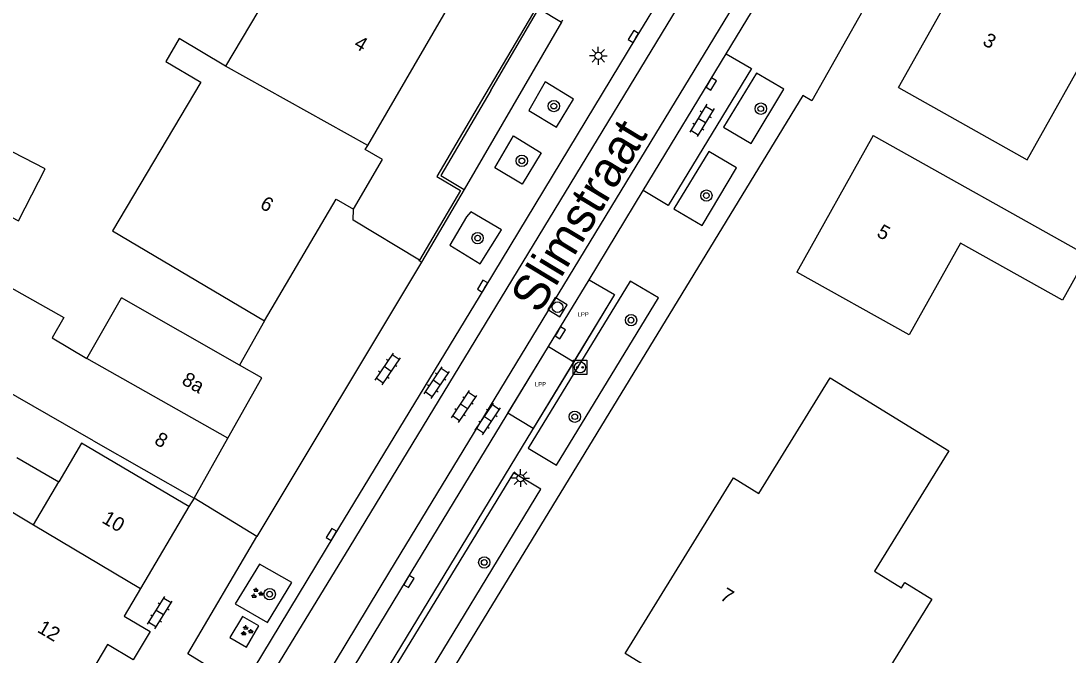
# Model space of a CAD drawing. Extents: x 136000 to 141014, y 402000 to 403500.
# Drawn here: x 137884.6 to 137958.3, y 402514.4 to 402559.1 of the extents above; entities that cross this region are included whole.
import ezdxf

# ---------------------------------------------------------------- set-up
doc = ezdxf.new("R2010")
doc.units = 0
for name, color, linetype in [('bp-grn-parkeervak', 7, 'Continuous'), ('gg-afsc-erfafscheiding', 7, 'Continuous'), ('gg-afsc-muur', 7, 'Continuous'), ('gg-anno-huisnummerreeks BGT', 7, 'Continuous'), ('gg-anno-openbare ruimte label', 7, 'Continuous'), ('gg-bbg-gedigitaliseerde bebouwing', 7, 'Continuous'), ('gg-bbg-gedigitaliseerde bijgebouw', 7, 'Continuous'), ('gg-bbg-hoofdgebouw', 7, 'Continuous'), ('gg-bbg-tussenscheiding', 7, 'Continuous'), ('gg-knt-verharding', 7, 'Continuous'), ('gg-knt-verharding nz', 7, 'Continuous'), ('gt-symb-boom', 7, 'Continuous'), ('gt-symb-groenvak', 7, 'Continuous'), ('gt-symb-klinker verharding', 7, 'Continuous'), ('gt-symb-kolk', 7, 'Continuous'), ('gt-symb-laadpunt elektrisch vervoer', 7, 'Continuous'), ('gt-symb-lichtmast', 7, 'Continuous'), ('gt-symb-rioolschacht', 7, 'Continuous'), ('kenmerkpunt laadpunt parkeerplaats', 7, 'Continuous')]:
    doc.layers.add(name, color=color, linetype=linetype)

# ---------------------------------------------------------------- blocks, each defined once
blk = doc.blocks.new('gt0-BOOM')
at = {"layer": 'gt-symb-boom'}
for radius in [0.4, 0.2]:
    blk.add_circle((0, 0), radius, dxfattribs=at)
blk = doc.blocks.new('gt0-LMAST')
at = {"layer": 'gt-symb-lichtmast'}
for p, q in [((-0.182, 0.173), (-0.447, 0.438)), ((-0.005, 0.246), (-0.005, 0.621)), ((0.172, 0.173), (0.437, 0.438)), ((-0.255, -0.004), (-0.63, -0.004)), ((-0.182, -0.181), (-0.447, -0.446)), ((-0.005, -0.254), (-0.005, -0.629)), ((0.437, -0.446), (0.172, -0.181)), ((0.245, -0.004), (0.62, -0.004))]:
    blk.add_line(p, q, dxfattribs=at)
blk.add_circle((-0.005, -0.004), 0.25, dxfattribs=at)
blk = doc.blocks.new('gt0-KOLK')
at = {"layer": 'gt-symb-kolk'}
blk.add_lwpolyline([(0, 0), (0.375, 0), (0.375, 0.4), (-0.375, 0.4), (-0.375, 0), (0, 0)], dxfattribs=at)
blk = doc.blocks.new('gt0-KL1')
at = {"layer": 'gt-symb-klinker verharding'}
for p, q in [((-1.15, 0.3), (1.15, 0.3)), ((-1, -0.3), (-1, 0.3)), ((-0.5, 0.3), (-0.5, 0.45)), ((0, -0.3), (0, 0.3)), ((0.5, 0.3), (0.5, 0.45)), ((1, -0.3), (1, 0.3)), ((-1.15, -0.3), (1.15, -0.3)), ((-0.5, -0.45), (-0.5, -0.3)), ((0.5, -0.45), (0.5, -0.3))]:
    blk.add_line(p, q, dxfattribs=at)
blk = doc.blocks.new('gt0-LEV')
at = {"layer": 'gt-symb-laadpunt elektrisch vervoer'}
blk.add_lwpolyline([(-0.486, 0.501), (0.486, 0.501), (0.486, -0.499), (-0.486, -0.499)], close=True, dxfattribs=at)
for centre, radius in [((0, 0), 0.393), ((-0.186, 0), 0.0566), ((0.186, 0), 0.0566)]:
    blk.add_circle(centre, radius, dxfattribs=at)
blk = doc.blocks.new('gt0-RS')
at = {"layer": 'gt-symb-rioolschacht'}
blk.add_lwpolyline([(-0.5, -0.5), (0.5, -0.5), (0.5, 0.5), (-0.5, 0.5)], close=True, dxfattribs=at)
blk.add_circle((0, 0), 0.375, dxfattribs=at)
blk = doc.blocks.new('gt0-GRVAK')
at = {"layer": 'gt-symb-groenvak'}
for p, q in [((-0.11, 0.189), (-0.228, 0.24)), ((-0.182, 0.153), (0.088, 0.153)), ((-0.091, 0.211), (-0.156, 0.322)), ((-0.047, 0.214), (-0.047, 0.393)), ((-0.004, 0.211), (0.061, 0.322)), ((0.015, 0.189), (0.133, 0.24)), ((0.262, -0.052), (0.197, 0.059)), ((0.305, -0.049), (0.305, 0.13)), ((0.349, -0.052), (0.414, 0.059)), ((-0.245, -0.228), (-0.363, -0.177)), ((-0.318, -0.264), (-0.047, -0.264)), ((-0.226, -0.206), (-0.291, -0.095)), ((-0.183, -0.203), (-0.183, -0.024)), ((-0.139, -0.206), (-0.074, -0.095)), ((-0.12, -0.228), (-0.002, -0.177)), ((0.243, -0.074), (0.125, -0.023)), ((0.17, -0.11), (0.441, -0.11)), ((0.368, -0.074), (0.486, -0.023))]:
    blk.add_line(p, q, dxfattribs=at)

msp = doc.modelspace()

# ---------------------------------------------------------------- linework, layer by layer
at = {"layer": 'bp-grn-parkeervak'}
msp.add_line((137921.748, 402536.132), (137923.523, 402535.053), dxfattribs=at)
for points in [[(137921.748, 402536.132), (137924.604, 402540.829), (137926.405, 402539.797), (137923.523, 402535.053)], [(137923.523, 402535.053), (137920.668, 402530.355), (137918.892, 402531.435), (137921.748, 402536.132)]]:
    msp.add_lwpolyline(points, dxfattribs=at)
at = {"layer": 'gg-afsc-erfafscheiding'}
msp.add_line((137912.81, 402542.079), (137901.213, 402522.757), dxfattribs=at)
at = {"layer": 'gg-afsc-muur'}
for p, q in [((137920.985, 402560.188), (137917.271, 402553.864)), ((137922.666, 402558.982), (137922.766, 402559.15)), ((137915.817, 402547.202), (137912.81, 402542.079))]:
    msp.add_line(p, q, dxfattribs=at)
for points in [[(137917.683, 402554.17), (137921.068, 402559.931), (137922.666, 402558.982)], [(137917.683, 402554.17), (137914.161, 402548.174), (137915.817, 402547.202)], [(137917.271, 402553.864), (137913.888, 402548.103), (137915.544, 402547.131), (137912.666, 402542.227)], [(137912.81, 402542.079), (137912.638, 402542.18), (137912.666, 402542.227)]]:
    msp.add_lwpolyline(points, dxfattribs=at)
at = {"layer": 'gg-bbg-gedigitaliseerde bebouwing'}
for p, q in [((137905.17, 402566.29), (137899, 402555.887)), ((137889.251, 402535.283), (137891.678, 402539.56)), ((137899.987, 402534.816), (137891.678, 402539.56)), ((137889.703, 402529.495), (137896.79, 402525.46))]:
    msp.add_line(p, q, dxfattribs=at)
for points in [[(137899, 402555.887), (137895.748, 402557.822), (137894.795, 402556.221), (137897.274, 402554.745)], [(137946.39, 402554.38), (137955.452, 402549.288), (137960.411, 402558.113)], [(137897.274, 402554.745), (137891.049, 402544.28), (137901.75, 402537.94)], [(137944.6, 402550.99), (137959.698, 402542.544), (137957.939, 402539.403), (137950.761, 402543.422), (137947.137, 402536.949), (137939.22, 402541.38)], [(137889.703, 402529.495), (137870.645, 402540.432), (137873.77, 402545.981), (137887.612, 402538.185), (137886.802, 402536.746), (137889.251, 402535.283)], [(137941.59, 402533.94), (137949.933, 402528.802), (137944.7, 402520.318), (137946.608, 402519.142), (137946.842, 402519.522), (137948.738, 402518.353), (137945.546, 402513.177)], [(137896.43, 402524.88), (137888.87, 402529.326), (137887.27, 402526.599)], [(137941.602, 402511.055), (137939.161, 402507.097), (137927.14, 402514.52)]]:
    msp.add_lwpolyline(points, dxfattribs=at)
at = {"layer": 'gg-bbg-gedigitaliseerde bijgebouw'}
msp.add_line((137884.32, 402528.33), (137887.27, 402526.599), dxfattribs=at)
msp.add_lwpolyline([(137879.882, 402547.363), (137884.434, 402544.988), (137886.315, 402548.647), (137881.774, 402550.982)], dxfattribs=at)
at = {"layer": 'gg-bbg-hoofdgebouw'}
for p, q in [((137946.39, 402554.38), (137952.642, 402565.505)), ((137944.6, 402550.99), (137939.22, 402541.38)), ((137896.79, 402525.46), (137899.175, 402529.695)), ((137896.43, 402524.88), (137893.015, 402519.088)), ((137893.015, 402519.088), (137891.874, 402517.153)), ((137890.691, 402515.147), (137887.274, 402509.351))]:
    msp.add_line(p, q, dxfattribs=at)
for points in [[(137909.016, 402550.303), (137914.97, 402560.5), (137914.653, 402560.689)], [(137908.02, 402545.81), (137910.05, 402549.3), (137908.84, 402550.001), (137909.016, 402550.303)], [(137901.75, 402537.94), (137906.79, 402546.51), (137908.02, 402545.81)], [(137899.175, 402529.695), (137901.56, 402533.93), (137899.987, 402534.816)], [(137927.14, 402514.52), (137934.77, 402526.89), (137936.56, 402525.78), (137941.59, 402533.94)], [(137891.874, 402517.153), (137893.698, 402516.078), (137892.497, 402514.082), (137890.691, 402515.147)]]:
    msp.add_lwpolyline(points, dxfattribs=at)
at = {"layer": 'gg-bbg-tussenscheiding'}
for p, q in [((137909.016, 402550.303), (137899, 402555.887)), ((137899.175, 402529.695), (137889.251, 402535.283)), ((137885.486, 402523.589), (137887.27, 402526.599)), ((137882.55, 402525.343), (137885.486, 402523.589)), ((137885.486, 402523.589), (137893.015, 402519.088))]:
    msp.add_line(p, q, dxfattribs=at)
at = {"layer": 'gg-knt-verharding'}
for p, q in [((137948.321, 402567.71), (137940.29, 402553.43)), ((137934.259, 402556.743), (137936.441, 402560.336)), ((137928.418, 402547.119), (137934.259, 402556.743)), ((137924.604, 402540.829), (137928.418, 402547.119)), ((137921.748, 402536.132), (137924.604, 402540.829)), ((137901.75, 402537.94), (137899.987, 402534.816)), ((137896.79, 402525.46), (137896.43, 402524.88)), ((137901.213, 402522.757), (137896.79, 402525.46))]:
    msp.add_line(p, q, dxfattribs=at)
for points in [[(137937.991, 402575.472), (137933.732, 402567.485), (137927.892, 402557.867), (137917.272, 402540.292), (137906.632, 402522.804), (137886.464, 402489.46), (137874.86, 402470.206), (137854.072, 402435.831)], [(137934.066, 402551.577), (137936.014, 402550.437), (137938.327, 402554.254), (137936.387, 402555.398), (137934.066, 402551.577)], [(137921.519, 402554.774), (137920.353, 402552.762), (137922.316, 402551.583), (137923.495, 402553.56), (137921.519, 402554.774)], [(137940.29, 402553.43), (137939.65, 402553.82), (137914.357, 402512.335)], [(137919.291, 402550.97), (137921.24, 402549.786), (137919.894, 402547.568), (137917.962, 402548.725), (137919.291, 402550.97)], [(137930.58, 402545.836), (137932.556, 402544.663), (137934.984, 402548.72), (137933.043, 402549.866), (137930.58, 402545.836)], [(137912.666, 402542.227), (137907.99, 402545.04), (137908.02, 402545.81)], [(137916.275, 402545.631), (137915.965, 402545.277), (137914.788, 402543.266), (137916.942, 402541.955), (137918.431, 402544.351), (137916.275, 402545.631)], [(137920.316, 402528.983), (137922.302, 402527.784), (137929.497, 402539.567), (137927.495, 402540.729), (137920.316, 402528.983)], [(137889.938, 402483.63), (137891.595, 402486.339), (137901.644, 402502.988), (137911.749, 402519.686), (137921.748, 402536.132)], [(137911.644, 402510.369), (137921.215, 402526.081), (137919.275, 402527.251), (137909.704, 402511.538), (137910.928, 402510.8)], [(137893.14, 402505.498), (137897.955, 402513.499), (137896.344, 402514.492), (137901.213, 402522.757)], [(137899.686, 402518.011), (137901.968, 402516.699), (137903.683, 402519.51), (137901.402, 402520.821), (137899.686, 402518.011)], [(137899.321, 402515.645), (137900.488, 402514.976), (137901.358, 402516.461), (137900.19, 402517.131), (137899.321, 402515.645)]]:
    msp.add_lwpolyline(points, dxfattribs=at)
at = {"layer": 'gg-knt-verharding nz'}
msp.add_line((137922.666, 402558.982), (137915.817, 402547.202), dxfattribs=at)
for points in [[(137939.144, 402574.788), (137934.574, 402566.233), (137918.425, 402539.599), (137907.762, 402522.06), (137897.622, 402505.449), (137887.629, 402488.806), (137865.886, 402452.736), (137856.889, 402437.891), (137846.492, 402420.662)], [(137942.579, 402572.71), (137935.796, 402561.865), (137926.517, 402546.569), (137910.544, 402520.298), (137900.503, 402503.655), (137890.392, 402486.967), (137878.789, 402467.758), (137868.705, 402451.284), (137859.748, 402436.183), (137849.316, 402418.985)], [(137934.259, 402556.743), (137936.042, 402555.708), (137930.18, 402546.06), (137928.418, 402547.119)], [(137924.604, 402540.829), (137926.405, 402539.797), (137899.775, 402495.968), (137891.672, 402482.575)]]:
    msp.add_lwpolyline(points, dxfattribs=at)

# ---------------------------------------------------------------- block references
at = {"layer": 'gt-symb-boom'}
for p in [(137922.122, 402553.071), (137936.695, 402552.887), (137919.872, 402549.212), (137932.862, 402546.766), (137916.756, 402543.772), (137927.558, 402537.993), (137923.597, 402531.196), (137917.224, 402520.931), (137902.114, 402518.697)]:
    msp.add_blockref('gt0-BOOM', p, dxfattribs=at)
at = {"layer": 'gt-symb-groenvak'}
for p in [(137901.202, 402518.757), (137900.48, 402516.11)]:
    msp.add_blockref('gt0-GRVAK', p, dxfattribs=at)
at = {"layer": 'gt-symb-klinker verharding'}
for p, rotation in [((137932.548, 402552.063), -121.25848530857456), ((137910.426, 402534.558), 55.92839019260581), ((137913.875, 402533.595), 55.92839019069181), ((137915.8, 402531.911), 55.92839019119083), ((137917.484, 402531.029), 55.92839019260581), ((137894.384, 402517.393), 57.9946167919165)]:
    msp.add_blockref('gt0-KL1', p, dxfattribs=dict(at, rotation=rotation))
at = {"layer": 'gt-symb-kolk'}
for p, rotation in [((137927.892, 402557.867), 58.7345438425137), ((137933.035, 402554.728), -121.2474720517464), ((137917.272, 402540.292), 58.85771803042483), ((137922.407, 402537.203), -121.32359775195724), ((137906.632, 402522.804), 58.676402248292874), ((137911.749, 402519.686), -121.18243108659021)]:
    msp.add_blockref('gt0-KOLK', p, dxfattribs=dict(at, rotation=rotation))
at = {"layer": 'gt-symb-laadpunt elektrisch vervoer'}
msp.add_blockref('gt0-LEV', (137923.967, 402534.667), dxfattribs=at)
at = {"layer": 'gt-symb-lichtmast'}
for p in [(137925.26, 402556.614), (137919.782, 402526.874)]:
    msp.add_blockref('gt0-LMAST', p, dxfattribs=at)
at = {"layer": 'gt-symb-rioolschacht', "rotation": 58.212746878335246}
msp.add_blockref('gt0-RS', (137922.377, 402538.911), dxfattribs=at)

# ---------------------------------------------------------------- texts
at = {"layer": 'gg-anno-huisnummerreeks BGT'}
for s, rotation, p in [('4', 329.7, (137907.982, 402557.233)), ('3', 330.7, (137952.244, 402557.425)), ('6', 329.5, (137901.36, 402545.933)), ('5', 330.8, (137944.788, 402543.934)), ('8a', 330.6, (137895.853, 402533.532)), ('8', 330.6, (137893.924, 402529.315)), ('10', 329.5, (137890.234, 402523.775)), ('7', 328.3, (137933.756, 402518.367)), ('12', 329.5, (137885.69, 402516.069))]:
    msp.add_text(s, height=1, rotation=rotation, dxfattribs=at).set_placement(p)
at = {"layer": 'gg-anno-openbare ruimte label'}
msp.add_text('Slimstraat', height=2.5, rotation=58.9, dxfattribs=at).set_placement((137921.086, 402538.363))
at = {"layer": 'kenmerkpunt laadpunt parkeerplaats'}
for p in [(137923.799, 402538.253), (137920.792, 402533.333)]:
    msp.add_text('LPP', height=0.3, dxfattribs=at).set_placement(p)

doc.saveas('drawing.dxf')
